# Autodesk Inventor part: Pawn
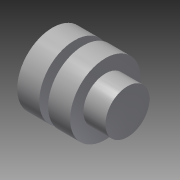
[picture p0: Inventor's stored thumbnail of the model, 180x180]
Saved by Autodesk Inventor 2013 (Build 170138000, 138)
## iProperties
Created: 2006-03
Part Number: Pawn
Document SubType Name: Modeling
Designer: debonom
Material: Stainless Steel, 440C
Mass: 19.8431 g
Surface Area: 13.6973 cm^2
Volume: 2.5604 cm^3
Density: 7.75 g/cm^3
Author: debonom
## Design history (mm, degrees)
sketch "Sketch1"
  geometry: L1 (0, 0)-(5, 0); L2 (5, 0)-(5, 5); L3 (5, 5)-(0, 5); L4 (0, 5)-(0, 0); L5 (5, 8)-(10, 8); L6 (10, 8)-(10, 0); L7 (10, 0)-(5, 0); L8 (5, 0)-(5, 8); L9 (10, 5)-(12, 5); L10 (12, 5)-(12, 0); L11 (12, 0)-(10, 0); L12 (10, 0)-(10, 5); L13 (-3.4, 0)-(20.4, 0) reference; L14 (12, 8)-(17, 8); L15 (17, 8)-(17, 0); L16 (17, 0)-(12, 0); L17 (12, 0)-(12, 8)
  constraints: 32 end point, 8 parallel, 7 collinear, 4 horizontal, 4 perpendicular, 1 point on line
  dimensions: "d0" = 5 distance of L2.end L3.end; "d1" = 5 distance of L3.end L1.start; "d2" = 8 distance between parallel lines of L13 L5; "d3" = 2 distance of L9.start L9.end; "d4" = 5 distance of L14.start L14.end; "d5" = 5 distance between parallel lines of L9 L13
revolve "Revolution1" sketch "Sketch1" stored, may be unused: angle "d6" = 90 deg
body "Solid1"
